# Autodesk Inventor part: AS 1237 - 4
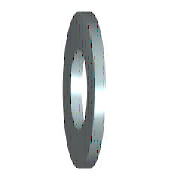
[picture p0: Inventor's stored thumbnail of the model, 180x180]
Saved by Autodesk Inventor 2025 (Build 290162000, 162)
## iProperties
Created: 2024-01
Part Number: AS 1237 - 4
Material: Acciaio, Dolce
Description: Rondella piatta in metallo per uso ingegneristico generico (serie metrica)
Document SubType Name: Modeling
Standard: AS 1237
Designer: R5800u
Standards Organization: AS
Language: it-IT
Size Designation: 4
Categories: <MemberInstance><Categories><Category DisplayName="Elementi di fissaggio" InternalName="e4da775c-781d-43d5-af7c-5136215cf5a6" Mnemonic="FSTN"><Category DisplayN
Density: 7.85 g/cm^3
Appearance: Semilucidato
IsCustomPart: 0
Author: R5800u
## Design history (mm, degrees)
body "Solid1"
sketch "Schizzo"
  geometry: C1 r 4 at (0, 0); C2 r 2.15 at (0, 0); 1 further point
  constraints: 2 centre point, 2 coincident
  dimensions: "d0" = 4.3 diameter of C2 (= SD1); "d1" = 8 diameter of C1 (= SD2)
extrude "Corpo" new body sketch "Schizzo" distance "d2" = 0.8 (= SD); taper "d3" = 0 deg
workaxis "Work Axis1"
workplane "Work Plane1"
other parameters: "SD1" = 4.3 [user parameter; used in 1 equation term], "SD2" = 8 [user parameter; used in 1 equation term], "SD" = 0.8 [user parameter; used in 1 equation term], "d4" = 0, "d5" = 0, "d6" = 0, "d7" = 0, "NND" = 4 [user parameter]
